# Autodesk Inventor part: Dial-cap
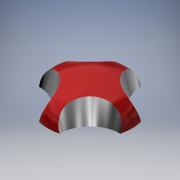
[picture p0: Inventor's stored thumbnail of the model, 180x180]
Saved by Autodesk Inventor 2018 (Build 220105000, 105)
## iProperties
Shininess: 64.0
Length Units: 11272
Angle Units: 11279
Time Units: 11290
Mass Units: 11286
Length Display Precision: 3
Angle Display Precision: 2
Compacted: True
Created: 2001-11
Part Number: Dial-cap
Document SubType Name: Modeling
Designer: Autodesk, Inc.
Mass: 1.44203 g
Surface Area: 10.3598 cm^2
Volume: 1.44203 cm^3
Density: 1 g/cm^3
Material: Generic
Appearance: Smooth - Red
Density: 0.0
Volumn: 0.0
Area: 0.0
PropertySet Name: Model Information
Control State: 0
Master: False
Checked Out: False
Author: Autodesk, Inc.
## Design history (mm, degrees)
sketch "Sketch1"
  geometry: L1 (133.744, 47.494)-(133.744, 91.062); L2 (145.889, 43.525)-(145.889, 43.609); L3 (138.904, 43.525)-(145.889, 43.525); L4 (138.904, 44.319)-(138.904, 43.525); L5 (136.7, 44.319)-(138.904, 44.319); L6 (136.7, 47.494)-(136.7, 44.319); L7 (133.744, 47.494)-(136.7, 47.494); L8 (133.744, 54.846)-(133.744, 91.062); A1 r 23.812 centre (133.744, 26.857) between (141.999, 49.192) and (133.744, 50.669); A2 r 5.953 centre (139.936, 43.609) between (145.889, 43.609) and (141.999, 49.192)
  constraints: 16 end point, 4 point on circle, 4 vertical, 3 horizontal, 2 centre point, 2 point on line, 1 tangent, 1 other
revolve "RevolutionFull1" sketch "Sketch1" stored, may be unused: angle "d0" = 360 deg
sketch "Sketch3"
  geometry: A1 r 12.144 centre (0, 0) between (-2.977, -11.774) and (-11.774, -2.977) reference; A2 r 8.797 centre (-11.774, -11.774) between (-2.977, -11.774) and (-11.774, -2.977)
  constraints: 4 point on circle, 1 centre point
extrude "ExtrusionThru1" cut sketch "Sketch3" extent not by distance; stored distance "d3" = 3.302; taper "d4" = 15 deg
pattern_circular "PolarArray1" dims angle "d7" = 360 deg
sketch "Sketch5"
  geometry: L1 (-2.887, 1.667)-(-2.887, -1.667); L2 (0, 3.334)-(-2.887, 1.667); L3 (2.887, 1.667)-(0, 3.334); L4 (2.887, -1.667)-(2.887, 1.667); L5 (0, -3.334)-(2.887, -1.667); L6 (-2.887, -1.667)-(0, -3.334)
  constraints: 12 end point, 2 parallel, 2 vertical
extrude "ExtrusionToPlane1" cut sketch "Sketch5" stored distance "d8" = 3.302; taper "d9" = 0 deg
body "Solid1"
other parameters: "d1" = 0, "d2" = 0
